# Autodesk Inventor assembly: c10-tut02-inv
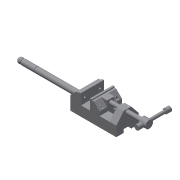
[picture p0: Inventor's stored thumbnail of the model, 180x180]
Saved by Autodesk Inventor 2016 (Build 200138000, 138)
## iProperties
Created: 2009-05
Part Number: c10-tut02-inv
Document SubType Name: Assembly
Designer: Sham
Author: Sham
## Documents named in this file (9)
- D:\KAVITA\Autodesk Inventor_ 2016 Project_Kavita\Inventor_Part Files\Inventor_2016_tut\c10_Inv_tut_2015\c10_tut02_inv\Drill Press Vice\c10-tut02-inv.iam
- D:\KAVITA\Autodesk Inventor_ 2016 Project_Kavita\Inventor_Part Files\Inventor_2016_tut\c10_Inv_tut_2015\c10_tut02_inv\Drill Press Vice\Base.ipt
- D:\KAVITA\Autodesk Inventor_ 2016 Project_Kavita\Inventor_Part Files\Inventor_2016_tut\c10_Inv_tut_2015\c10_tut02_inv\Drill Press Vice\Safety Handle.ipt
- D:\KAVITA\Autodesk Inventor_ 2016 Project_Kavita\Inventor_Part Files\Inventor_2016_tut\c10_Inv_tut_2015\c10_tut02_inv\Drill Press Vice\Jaw Face.ipt
- D:\KAVITA\Autodesk Inventor_ 2016 Project_Kavita\Inventor_Part Files\Inventor_2016_tut\c10_Inv_tut_2015\c10_tut02_inv\Drill Press Vice\Movable Jaw.ipt
- D:\KAVITA\Autodesk Inventor_ 2016 Project_Kavita\Inventor_Part Files\Inventor_2016_tut\c10_Inv_tut_2015\c10_tut02_inv\Drill Press Vice\Cap Screw.ipt
- D:\KAVITA\Autodesk Inventor_ 2016 Project_Kavita\Inventor_Part Files\Inventor_2016_tut\c10_Inv_tut_2015\c10_tut02_inv\Drill Press Vice\Clamp Screw Handle.ipt
- D:\KAVITA\Autodesk Inventor_ 2016 Project_Kavita\Inventor_Part Files\Inventor_2016_tut\c10_Inv_tut_2015\c10_tut02_inv\Drill Press Vice\Clamp Screw.ipt
- D:\KAVITA\Autodesk Inventor_ 2016 Project_Kavita\Inventor_Part Files\Inventor_2016_tut\c10_Inv_tut_2015\c10_tut02_inv\Drill Press Vice\Handle Stop.ipt
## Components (11 placed, 8 different names)
1. Base:1 — Mate:2, Mate:3, Mate:7, Insert:10, Insert:11
2. Safety Handle:1
3. Jaw Face:1 — Insert:8, Insert:9, Mate:7
4. Jaw Face:2 — Insert:10, Insert:11
5. Movable Jaw:1 — Mate:2, Mate:3, Insert:2, Insert:3, Insert:4, Insert:8, Insert:9
6. Cap Screw:1 — Insert:2
7. Cap Screw:2 — Insert:3
8. Clamp Screw:1 — Insert:4, Mate:6, Rotation/Translation:2
9. Clamp Screw Handle:1 — Mate:6, Insert:5, Insert:6, Rotation/Translation:2
10. Handle Stop:1 — Insert:6, Mate:8
11. Handle Stop:2 — Insert:5
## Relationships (15: Insert 9, Mate 5, RelateRotateTranslate 1)
- Mate:2: Base:1 ↔ Movable Jaw:1
- Mate:3: Base:1 ↔ Movable Jaw:1
- Insert:2: Movable Jaw:1 ↔ Cap Screw:1
- Insert:3: Movable Jaw:1 ↔ Cap Screw:2
- Insert:4: Movable Jaw:1 ↔ Clamp Screw:1
- Mate:6: Clamp Screw:1 ↔ Clamp Screw Handle:1
- Insert:5: Clamp Screw Handle:1 ↔ Handle Stop:2
- Insert:6: Clamp Screw Handle:1 ↔ Handle Stop:1
- Insert:8: Jaw Face:1 ↔ Movable Jaw:1
- Insert:9: Jaw Face:1 ↔ Movable Jaw:1
- Mate:7: Base:1 ↔ Jaw Face:1
- Rotation/Translation:2 [RelateRotateTranslate]: Clamp Screw:1 ↔ Clamp Screw Handle:1
- Mate:8: Handle Stop:1
- Insert:10: Base:1 ↔ Jaw Face:2
- Insert:11: Base:1 ↔ Jaw Face:2
